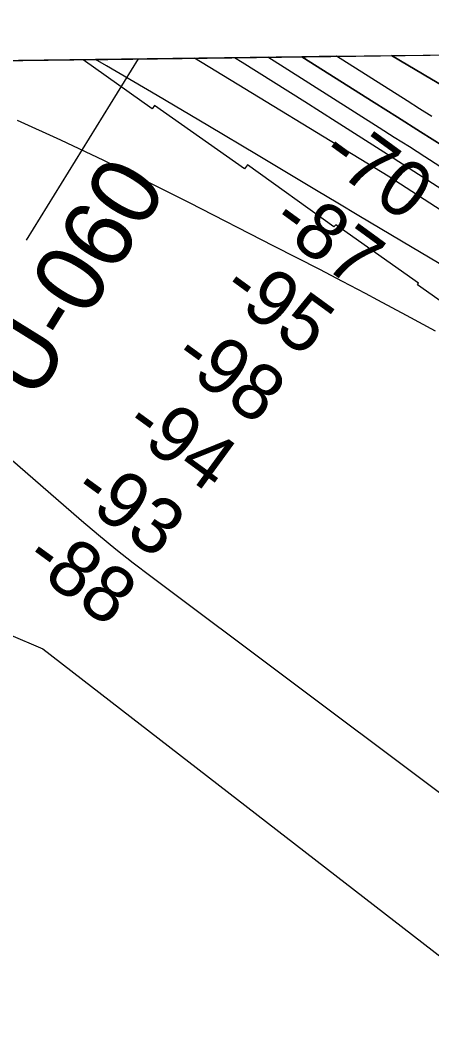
# Model space of a CAD drawing. Extents: x 3753511 to 3791668, y 379550 to 405377.
# Drawn here: x 3757586 to 3758078, y 401981 to 403200 of the extents above; entities that cross this region are included whole.
import ezdxf

# ---------------------------------------------------------------- set-up
doc = ezdxf.new("R2010")
doc.units = 0
for name, color, linetype in [('V-GRID-FRAM', 7, 'Continuous'), ('V-RIVR-RANG', 7, 'Continuous'), ('V-RIVR-RANG-IDEN', 7, 'Continuous'), ('V-RRAP-RVMT', 7, 'Continuous'), ('V-TOPO-DPTH', 7, 'Continuous'), ('V-TOPO-MAJR', 7, 'Continuous'), ('V-TOPO-MINR', 7, 'Continuous')]:
    doc.layers.add(name, color=color, linetype=linetype)

msp = doc.modelspace()

# ---------------------------------------------------------------- linework, layer by layer
at = {"layer": 'V-GRID-FRAM'}
msp.add_lwpolyline([(3757521.7, 403151.1), (3789298.9, 403581), (3789552.8, 385400.3), (3757759.7, 384970.3), (3757521.7, 403151.1)], dxfattribs=at)
at = {"layer": 'V-RIVR-RANG'}
msp.add_line((3757726.8, 403153.9), (3757593.1, 402937.2), dxfattribs=at)
at = {"layer": 'V-RRAP-RVMT'}
for p, q in [((3757661, 403153), (3758244.3, 403160.9)), ((3757743.8, 403094.3), (3757661, 403153)), ((3757746.5, 403098.3), (3757743.8, 403094.3)), ((3757854.2, 403022.5), (3757746.5, 403098.3)), ((3757857.7, 403027.2), (3757854.2, 403022.5)), ((3757961.1, 402953.4), (3757857.7, 403027.2)), ((3757963.3, 402955.6), (3757961.1, 402953.4)), ((3758062.1, 402886.1), (3757963.3, 402955.6)), ((3758060.9, 402884), (3758062.1, 402886.1)), ((3758173.8, 402804.4), (3758060.9, 402884))]:
    msp.add_line(p, q, dxfattribs=at)
at = {"layer": 'V-TOPO-DPTH'}
for p, q in [((3757964.1, 403157.1), (3757922.6, 403156.5)), ((3757964.1, 403157.1), (3758030, 403158)), ((3758030, 403158), (3758130, 403159.3))]:
    msp.add_line(p, q, dxfattribs=at)
for points in [[(3758092.4, 403049.2), (3758064.7, 403066.7), (3758037, 403084.3), (3758009.3, 403101.8), (3757922.6, 403156.5), (3757521.7, 403151.1)], [(3757922.6, 403156.5), (3758009.3, 403101.8), (3758037, 403084.3), (3758064.7, 403066.7), (3758092.4, 403049.2)], [(3758078.2, 403085.2), (3758063.5, 403094.5), (3758048.7, 403103.8), (3757964.1, 403157.1)], [(3758078.2, 403085.2), (3758063.5, 403094.5), (3758048.7, 403103.8), (3757964.1, 403157.1)], [(3759459.6, 402182), (3758866.1, 402620.1), (3758840.2, 402639.1), (3758814.1, 402657.8), (3758787.8, 402676.2), (3758761.3, 402694.4), (3758582.6, 402815.6), (3758503.8, 402868.1), (3758424.5, 402919.6), (3758344.2, 402969.8), (3758263.4, 403019.1), (3758124, 403102.5), (3758112.4, 403109.4), (3758100.9, 403116.2), (3758089.4, 403123.1), (3758077.8, 403129.9), (3758030, 403158)], [(3758030, 403158), (3758077.8, 403129.9), (3758089.4, 403123.1), (3758100.9, 403116.2), (3758112.4, 403109.4), (3758124, 403102.5), (3758263.4, 403019.1), (3758344.2, 402969.8), (3758424.5, 402919.6), (3758503.8, 402868.1), (3758582.6, 402815.6), (3758761.3, 402694.4), (3758787.8, 402676.2), (3758814.1, 402657.8), (3758840.2, 402639.1), (3758866.1, 402620.1), (3759459.6, 402182)]]:
    msp.add_lwpolyline(points, dxfattribs=at)
at = {"layer": 'V-TOPO-MAJR'}
msp.add_lwpolyline([(3759069.4, 402376.9), (3759008.6, 402419.3), (3758947.7, 402461.5), (3758886.7, 402503.5), (3758828.4, 402543.5), (3758796.4, 402565.3), (3758764.3, 402587), (3758732, 402608.4), (3758699.6, 402629.7), (3758492.6, 402764.6), (3758419.2, 402812.2), (3758345.9, 402859.8), (3758272.4, 402907.1), (3758198.8, 402954.4), (3758087.9, 403025.4), (3758069.7, 403037.1), (3758051.5, 403048.7), (3758033.3, 403060.2), (3758015.1, 403071.8), (3757901.6, 403143.7), (3757882.1, 403156)], dxfattribs=at)
at = {"layer": 'V-TOPO-MINR'}
for points in [[(3758119.4, 402890.5), (3758042, 402936.2), (3758016.5, 402951.2), (3757991, 402966.3), (3757965.6, 402981.5), (3757940.2, 402996.7), (3757870.5, 403038.6), (3757810.1, 403074.5), (3757749.6, 403110.3), (3757688.9, 403145.6), (3757675.9, 403153.2)], [(3759550.4, 401984.4), (3758763.3, 402531.7), (3758750.6, 402540.5), (3758737.7, 402549.3), (3758724.9, 402558), (3758711.9, 402566.7), (3758648.1, 402609.3), (3758603.2, 402639.1), (3758558.2, 402668.9), (3758513.1, 402698.4), (3758467.9, 402727.8), (3758026.1, 403013.9), (3757794.2, 403154.8)], [(3759146.6, 402293.5), (3758794.3, 402537.2), (3758772.4, 402552.3), (3758750.4, 402567.3), (3758728.3, 402582.1), (3758706.2, 402596.9), (3758601.2, 402666.3), (3758526.4, 402715.5), (3758451.5, 402764.5), (3758376.5, 402813.3), (3758301.3, 402861.9), (3758056.5, 403019.5), (3758047.5, 403025.3), (3758038.6, 403031), (3758029.6, 403036.8), (3758020.7, 403042.5), (3757963.7, 403078.7), (3757926.2, 403102.5), (3757888.7, 403126.2), (3757851.2, 403149.8), (3757842.2, 403155.4)], [(3758092.4, 403049.2), (3758064.7, 403066.7), (3758037, 403084.3), (3758009.3, 403101.8), (3757922.6, 403156.5)], [(3758078.2, 403085.2), (3758063.5, 403094.5), (3758048.7, 403103.8), (3757964.1, 403157.1)], [(3759459.6, 402182), (3758866.1, 402620.1), (3758840.2, 402639.1), (3758814.1, 402657.8), (3758787.8, 402676.2), (3758761.3, 402694.4), (3758582.6, 402815.6), (3758503.8, 402868.1), (3758424.5, 402919.6), (3758344.2, 402969.8), (3758263.4, 403019.1), (3758124, 403102.5), (3758112.4, 403109.4), (3758100.9, 403116.2), (3758089.4, 403123.1), (3758077.8, 403129.9), (3758030, 403158)], [(3758082.6, 402828.7), (3758048.1, 402847.3), (3758013.5, 402865.7), (3757998.7, 402873.5), (3757971.5, 402887.9), (3757944.1, 402902.1), (3757916.8, 402916.3), (3757889.3, 402930.3), (3757788.3, 402981.9), (3757737.2, 403007.4), (3757686, 403032.5), (3757634.3, 403056.8), (3757582.5, 403080.5)], [(3757527.4, 402716.8), (3757659.3, 402602.3), (3757679.6, 402585.1), (3757700.1, 402568.2), (3757721, 402551.7), (3757742.1, 402535.6), (3758074.7, 402286.6), (3758127, 402247.7), (3758179.3, 402208.9), (3758231.9, 402170.4), (3758284.5, 402131.9), (3758368.2, 402071.1), (3758379, 402063.2), (3758389.9, 402055.3), (3758400.7, 402047.4), (3758411.5, 402039.6), (3758602.9, 401900.3), (3758702.7, 401828.5), (3758803.1, 401757.4), (3758904.2, 401687.4), (3759005.9, 401618.2), (3759203.7, 401485.2)], [(3757530.4, 402484), (3757612.8, 402448.9), (3758265.6, 401944), (3758280.6, 401932.6), (3758295.7, 401921.6), (3758311, 401910.8), (3758326.5, 401900.3), (3758469.7, 401805.1), (3758557.7, 401748.7), (3758646.9, 401694.2), (3758737.9, 401642.6), (3758830, 401593), (3758977.7, 401516.5), (3758997.9, 401506), (3759018.1, 401495.4), (3759038.2, 401484.7)]]:
    msp.add_lwpolyline(points, dxfattribs=at)

# ---------------------------------------------------------------- texts
at = {"layer": 'V-RIVR-RANG'}
for s, p in [('-70', (3757941.9, 403033.7)), ('-87', (3757882.9, 402953)), ('-95', (3757823.6, 402872.4)), ('-98', (3757765.5, 402791.1)), ('-94', (3757707.1, 402709.9)), ('-93', (3757645.3, 402631.2)), ('-88', (3757587.5, 402549.6))]:
    msp.add_text(s, height=67, rotation=323.9586, dxfattribs=at).set_placement(p)
at = {"layer": 'V-RIVR-RANG-IDEN'}
msp.add_text('U-060', height=83, rotation=58.1763, dxfattribs=at).set_placement((3757603.4, 402743.1))

doc.saveas('drawing.dxf')
